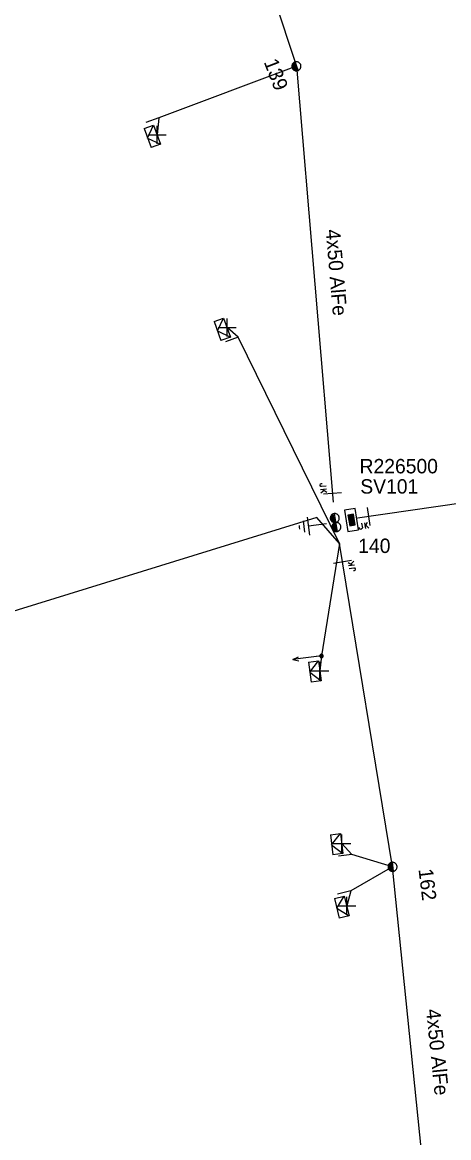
# Model space of a CAD drawing. Extents: x -544780 to -541582, y -1198995 to -1196551.
# Drawn here: x -542549.7 to -542520.2, y -1198913.7 to -1198836.4 of the extents above; entities that cross this region are included whole.
import ezdxf

# ---------------------------------------------------------------- set-up
doc = ezdxf.new("R2010")
doc.units = 0
for name, color, linetype in [('Vrstva 1', 7, 'Continuous'), ('Vrstva 13', 7, 'Continuous'), ('Vrstva 14', 7, 'Continuous'), ('Vrstva 15', 7, 'Continuous'), ('Vrstva 18', 7, 'Continuous'), ('Vrstva 2', 7, 'Continuous'), ('Vrstva 28', 7, 'Continuous'), ('Vrstva 29', 7, 'Continuous'), ('Vrstva 30', 7, 'Continuous'), ('Vrstva 31', 7, 'Continuous'), ('Vrstva 34', 7, 'Continuous'), ('Vrstva 54', 7, 'Continuous'), ('Vrstva 59', 7, 'Continuous'), ('Vrstva 8', 7, 'Continuous'), ('Vrstva 9', 7, 'Continuous')]:
    doc.layers.add(name, color=color, linetype=linetype)

# ---------------------------------------------------------------- blocks, each defined once
blk = doc.blocks.new('NN440')
at = {"layer": 'Vrstva 2'}
for points in [[(0.63, 0), (0.63, 0.06), (0.62, 0.13), (0.6, 0.19), (0.58, 0.25), (0.55, 0.31), (0.51, 0.37), (0.47, 0.42), (0.42, 0.46), (0.37, 0.51), (0.32, 0.54), (0.26, 0.57), (0.2, 0.59), (0.13, 0.61), (0.07, 0.62), (0, 0.63), (-0.06, 0.62), (-0.13, 0.61), (-0.19, 0.59), (-0.26, 0.57), (-0.31, 0.54), (-0.37, 0.51), (-0.42, 0.46), (-0.47, 0.42), (-0.51, 0.37), (-0.54, 0.31), (-0.57, 0.25), (-0.6, 0.19), (-0.62, 0.13), (-0.63, 0.06), (-0.63, 0), (-0.63, -0.07), (-0.62, -0.14), (-0.6, -0.2), (-0.57, -0.26), (-0.54, -0.32), (-0.51, -0.37), (-0.47, -0.43), (-0.42, -0.47), (-0.37, -0.51), (-0.31, -0.55), (-0.26, -0.58), (-0.19, -0.6), (-0.13, -0.62), (-0.06, -0.63), (0, -0.63), (0.07, -0.63), (0.13, -0.62), (0.2, -0.6), (0.26, -0.58), (0.32, -0.55), (0.37, -0.51), (0.42, -0.47), (0.47, -0.43), (0.51, -0.37), (0.55, -0.32), (0.58, -0.26), (0.6, -0.2), (0.62, -0.14), (0.63, -0.07), (0.63, 0)], [(-0.63, 0), (0.63, 0)], [(-0.6, -0.18), (0.57, -0.18)], [(-0.51, -0.32), (0.5, -0.32)], [(-0.37, -0.47), (0.35, -0.47)]]:
    blk.add_lwpolyline(points, dxfattribs=at)
blk = doc.blocks.new('NN450')
at = {"layer": 'Vrstva 2'}
for points in [[(0, 0), (0, 0.07), (-0.01, 0.13), (-0.03, 0.19), (-0.05, 0.25), (-0.08, 0.31), (-0.12, 0.37), (-0.16, 0.42), (-0.21, 0.46), (-0.26, 0.51), (-0.31, 0.54), (-0.37, 0.57), (-0.43, 0.59), (-0.5, 0.61), (-0.56, 0.62), (-0.63, 0.62), (-0.69, 0.62), (-0.75, 0.61), (-0.82, 0.59), (-0.88, 0.57), (-0.94, 0.54), (-0.99, 0.51), (-1.04, 0.46), (-1.09, 0.42), (-1.13, 0.37), (-1.17, 0.31), (-1.2, 0.25), (-1.22, 0.19), (-1.24, 0.13), (-1.25, 0.07), (-1.25, 0), (-1.25, -0.07), (-1.24, -0.13), (-1.22, -0.19), (-1.2, -0.25), (-1.17, -0.31), (-1.13, -0.37), (-1.09, -0.42), (-1.04, -0.46), (-0.99, -0.51), (-0.94, -0.54), (-0.88, -0.57), (-0.82, -0.59), (-0.75, -0.61), (-0.69, -0.62), (-0.62, -0.63), (-0.56, -0.62), (-0.5, -0.61), (-0.43, -0.59), (-0.37, -0.57), (-0.31, -0.54), (-0.26, -0.51), (-0.21, -0.46), (-0.16, -0.42), (-0.12, -0.37), (-0.08, -0.31), (-0.05, -0.25), (-0.03, -0.19), (-0.01, -0.13), (0, -0.07), (0, 0)], [(1.25, 0), (1.25, 0.07), (1.24, 0.13), (1.22, 0.19), (1.2, 0.25), (1.17, 0.31), (1.13, 0.37), (1.09, 0.42), (1.04, 0.46), (0.99, 0.51), (0.94, 0.54), (0.88, 0.57), (0.82, 0.59), (0.75, 0.61), (0.69, 0.62), (0.62, 0.62), (0.56, 0.62), (0.5, 0.61), (0.43, 0.59), (0.37, 0.57), (0.31, 0.54), (0.26, 0.51), (0.21, 0.46), (0.16, 0.42), (0.12, 0.37), (0.08, 0.31), (0.05, 0.25), (0.03, 0.19), (0.01, 0.13), (0, 0.07), (0, 0), (0, -0.07), (0.01, -0.13), (0.03, -0.19), (0.05, -0.25), (0.08, -0.31), (0.12, -0.37), (0.16, -0.42), (0.21, -0.46), (0.26, -0.51), (0.31, -0.54), (0.37, -0.57), (0.43, -0.59), (0.5, -0.61), (0.56, -0.62), (0.63, -0.63), (0.69, -0.62), (0.75, -0.61), (0.82, -0.59), (0.88, -0.57), (0.94, -0.54), (0.99, -0.51), (1.04, -0.46), (1.09, -0.42), (1.13, -0.37), (1.17, -0.31), (1.2, -0.25), (1.22, -0.19), (1.24, -0.13), (1.25, -0.07), (1.25, 0)], [(-1.25, 0), (1.25, 0)], [(-1.23, -0.16), (-0.02, -0.16)], [(-1.16, -0.32), (-0.09, -0.32)], [(-1.03, -0.47), (-0.22, -0.47)], [(0.02, -0.16), (1.23, -0.16)], [(0.09, -0.32), (1.16, -0.32)], [(0.22, -0.47), (1.03, -0.47)]]:
    blk.add_lwpolyline(points, dxfattribs=at)
blk = doc.blocks.new('NN560')
at = {"layer": 'Vrstva 2'}
for points in [[(1.999, -0.001), (1.59, 0.141)], [(0, -0.001), (1.999, -0.001)], [(1.999, -0.001), (1.59, -0.134)]]:
    blk.add_lwpolyline(points, dxfattribs=at)
blk = doc.blocks.new('NN840')
at = {"layer": 'Vrstva 15'}
for points in [[(0.003, 0.619), (0.003, -0.631)], [(-0.745, -0.71), (-0.745, -0.66)], [(-0.73, -0.764), (-0.745, -0.71)], [(-0.657, -0.798), (-0.73, -0.764)], [(-0.558, -0.764), (-0.627, -0.798)], [(-0.538, -0.71), (-0.558, -0.764)], [(-0.538, -0.385), (-0.538, -0.71)], [(-0.332, -0.385), (-0.332, -0.798)], [(-0.332, -0.641), (-0.125, -0.385)], [(-0.263, -0.557), (-0.091, -0.798)], [(-0.627, -0.798), (-0.657, -0.798)]]:
    blk.add_lwpolyline(points, dxfattribs=at)
blk = doc.blocks.new('NN800')
at = {"layer": 'Vrstva 1'}
for points in [[(-0.442, 0.442), (0.442, -0.442)], [(-0.442, -0.442), (0.442, 0.442)]]:
    blk.add_lwpolyline(points, dxfattribs=at)
blk = doc.blocks.new('NN620')
at = {"layer": 'Vrstva 8'}
for points in [[(0.752, 0.004), (-0.748, 0.004)], [(-0.748, 0.004), (-0.748, -0.746)], [(0.752, -0.746), (0.752, 0.004)], [(-0.748, -0.746), (0.752, -0.746)], [(0.368, -0.18), (-0.376, -0.18)], [(-0.376, -0.18), (-0.376, -0.558)], [(-0.376, -0.558), (0.368, -0.558)], [(0.321, -0.227), (-0.329, -0.227)], [(-0.329, -0.227), (-0.329, -0.51)], [(-0.329, -0.51), (0.321, -0.51)], [(0.274, -0.274), (-0.281, -0.274)], [(-0.281, -0.274), (-0.281, -0.463)], [(-0.281, -0.463), (0.274, -0.463)], [(0.227, -0.321), (-0.234, -0.321)], [(-0.234, -0.321), (-0.234, -0.416)], [(-0.234, -0.416), (0.227, -0.416)], [(-0.193, -0.369), (0.185, -0.369)], [(0.227, -0.416), (0.227, -0.321)], [(0.274, -0.463), (0.274, -0.274)], [(0.321, -0.51), (0.321, -0.227)], [(0.368, -0.558), (0.368, -0.18)]]:
    blk.add_lwpolyline(points, dxfattribs=at)
blk = doc.blocks.new('NN630')
at = {"layer": 'Vrstva 9'}
for points in [[(-0.003, -0.7), (-0.703, 0)], [(-0.703, -0.7), (-0.703, 0), (0.697, 0), (0.697, -0.7)], [(-0.703, -0.7), (0.697, -0.7)], [(-0.003, -0.7), (0.697, 0)]]:
    blk.add_lwpolyline(points, dxfattribs=at)
blk = doc.blocks.new('NN810')
at = {"layer": 'Vrstva 14'}
for points in [[(0.004, -0.64), (0.004, -1.89)], [(0.629, -1.89), (-0.621, -1.89)], [(0.388, -2.2), (-0.399, -2.2)], [(0.004, -2.515), (-0.124, -2.515)], [(0.137, -2.515), (0.004, -2.515)]]:
    blk.add_lwpolyline(points, dxfattribs=at)
blk = doc.blocks.new('NN500')
at = {"layer": 'Vrstva 2'}
for points in [[(0, -0.24), (0.02, -0.23), (0.05, -0.23), (0.07, -0.22), (0.09, -0.22), (0.12, -0.2), (0.14, -0.19), (0.16, -0.18), (0.17, -0.16), (0.19, -0.14), (0.2, -0.12), (0.21, -0.1), (0.22, -0.07), (0.23, -0.05), (0.23, -0.02), (0.23, 0), (0.23, 0.02), (0.23, 0.05), (0.22, 0.07), (0.21, 0.1), (0.2, 0.12), (0.19, 0.14), (0.17, 0.16), (0.16, 0.17), (0.14, 0.19), (0.12, 0.2), (0.09, 0.21), (0.07, 0.22), (0.05, 0.23), (0.02, 0.23), (0, 0.23), (-0.03, 0.23), (-0.05, 0.23), (-0.07, 0.22), (-0.1, 0.21), (-0.12, 0.2), (-0.14, 0.19), (-0.16, 0.17), (-0.18, 0.16), (-0.19, 0.14), (-0.2, 0.12), (-0.22, 0.1), (-0.22, 0.07), (-0.23, 0.05), (-0.23, 0.02), (-0.24, 0), (-0.23, -0.02), (-0.23, -0.05), (-0.22, -0.07), (-0.22, -0.1), (-0.2, -0.12), (-0.19, -0.14), (-0.18, -0.16), (-0.16, -0.18), (-0.14, -0.19), (-0.12, -0.2), (-0.1, -0.22), (-0.07, -0.22), (-0.05, -0.23), (-0.03, -0.23), (0, -0.24)], [(0, -0.24), (0.02, -0.23), (0.05, -0.23), (0.07, -0.22), (0.09, -0.22), (0.12, -0.2), (0.14, -0.19), (0.16, -0.18), (0.17, -0.16), (0.19, -0.14), (0.2, -0.12), (0.21, -0.1), (0.22, -0.07), (0.23, -0.05), (0.23, -0.02), (0.23, 0), (0.23, 0.02), (0.23, 0.05), (0.22, 0.07), (0.21, 0.1), (0.2, 0.12), (0.19, 0.14), (0.17, 0.16), (0.16, 0.17), (0.14, 0.19), (0.12, 0.2), (0.09, 0.21), (0.07, 0.22), (0.05, 0.23), (0.02, 0.23), (0, 0.23), (-0.03, 0.23), (-0.05, 0.23), (-0.07, 0.22), (-0.1, 0.21), (-0.12, 0.2), (-0.14, 0.19), (-0.16, 0.17), (-0.18, 0.16), (-0.19, 0.14), (-0.2, 0.12), (-0.22, 0.1), (-0.22, 0.07), (-0.23, 0.05), (-0.23, 0.02), (-0.24, 0), (-0.23, -0.02), (-0.23, -0.05), (-0.22, -0.07), (-0.22, -0.1), (-0.2, -0.12), (-0.19, -0.14), (-0.18, -0.16), (-0.16, -0.18), (-0.14, -0.19), (-0.12, -0.2), (-0.1, -0.22), (-0.07, -0.22), (-0.05, -0.23), (-0.03, -0.23), (0, -0.24)], [(0, -0.21), (0.02, -0.2), (0.04, -0.2), (0.06, -0.2), (0.08, -0.19), (0.1, -0.18), (0.12, -0.17), (0.14, -0.15), (0.15, -0.14), (0.16, -0.12), (0.18, -0.1), (0.19, -0.08), (0.19, -0.06), (0.2, -0.04), (0.2, -0.02), (0.2, 0), (0.2, 0.02), (0.2, 0.04), (0.19, 0.06), (0.19, 0.08), (0.18, 0.1), (0.16, 0.12), (0.15, 0.14), (0.14, 0.15), (0.12, 0.17), (0.1, 0.18), (0.08, 0.19), (0.06, 0.19), (0.04, 0.2), (0.02, 0.2), (0, 0.2), (-0.02, 0.2), (-0.04, 0.2), (-0.06, 0.19), (-0.08, 0.19), (-0.1, 0.18), (-0.12, 0.17), (-0.14, 0.15), (-0.15, 0.14), (-0.17, 0.12), (-0.18, 0.1), (-0.19, 0.08), (-0.2, 0.06), (-0.2, 0.04), (-0.21, 0.02), (-0.21, 0), (-0.21, -0.02), (-0.2, -0.04), (-0.2, -0.06), (-0.19, -0.08), (-0.18, -0.1), (-0.17, -0.12), (-0.15, -0.14), (-0.14, -0.15), (-0.12, -0.17), (-0.1, -0.18), (-0.08, -0.19), (-0.06, -0.2), (-0.04, -0.2), (-0.02, -0.2), (0, -0.21)], [(0, -0.18), (0.02, -0.18), (0.04, -0.17), (0.05, -0.17), (0.07, -0.16), (0.09, -0.15), (0.1, -0.14), (0.12, -0.13), (0.13, -0.12), (0.14, -0.1), (0.15, -0.09), (0.16, -0.07), (0.17, -0.05), (0.17, -0.04), (0.17, -0.02), (0.17, 0), (0.17, 0.02), (0.17, 0.04), (0.17, 0.05), (0.16, 0.07), (0.15, 0.09), (0.14, 0.1), (0.13, 0.12), (0.12, 0.13), (0.1, 0.14), (0.09, 0.15), (0.07, 0.16), (0.05, 0.17), (0.04, 0.17), (0.02, 0.17), (0, 0.18), (-0.02, 0.17), (-0.04, 0.17), (-0.06, 0.17), (-0.07, 0.16), (-0.09, 0.15), (-0.1, 0.14), (-0.12, 0.13), (-0.13, 0.12), (-0.14, 0.1), (-0.15, 0.09), (-0.16, 0.07), (-0.17, 0.05), (-0.17, 0.04), (-0.18, 0.02), (-0.18, 0), (-0.18, -0.02), (-0.17, -0.04), (-0.17, -0.05), (-0.16, -0.07), (-0.15, -0.09), (-0.14, -0.1), (-0.13, -0.12), (-0.12, -0.13), (-0.1, -0.14), (-0.09, -0.15), (-0.07, -0.16), (-0.06, -0.17), (-0.04, -0.17), (-0.02, -0.18), (0, -0.18)], [(0, -0.15), (0.01, -0.15), (0.03, -0.14), (0.04, -0.14), (0.06, -0.13), (0.07, -0.13), (0.08, -0.12), (0.1, -0.11), (0.11, -0.1), (0.12, -0.09), (0.13, -0.07), (0.13, -0.06), (0.14, -0.05), (0.14, -0.03), (0.14, -0.02), (0.14, 0), (0.14, 0.01), (0.14, 0.03), (0.14, 0.04), (0.13, 0.06), (0.13, 0.07), (0.12, 0.09), (0.11, 0.1), (0.1, 0.11), (0.08, 0.12), (0.07, 0.13), (0.06, 0.13), (0.04, 0.14), (0.03, 0.14), (0.01, 0.14), (0, 0.15), (-0.02, 0.14), (-0.03, 0.14), (-0.05, 0.14), (-0.06, 0.13), (-0.07, 0.13), (-0.09, 0.12), (-0.1, 0.11), (-0.11, 0.1), (-0.12, 0.09), (-0.13, 0.07), (-0.13, 0.06), (-0.14, 0.04), (-0.14, 0.03), (-0.15, 0.01), (-0.15, 0), (-0.15, -0.02), (-0.14, -0.03), (-0.14, -0.05), (-0.13, -0.06), (-0.13, -0.07), (-0.12, -0.09), (-0.11, -0.1), (-0.1, -0.11), (-0.09, -0.12), (-0.07, -0.13), (-0.06, -0.13), (-0.05, -0.14), (-0.03, -0.14), (-0.02, -0.15), (0, -0.15)], [(0, -0.12), (0.01, -0.12), (0.02, -0.11), (0.03, -0.11), (0.05, -0.11), (0.06, -0.1), (0.07, -0.09), (0.08, -0.09), (0.09, -0.08), (0.09, -0.07), (0.1, -0.06), (0.11, -0.05), (0.11, -0.04), (0.11, -0.02), (0.11, -0.01), (0.12, 0), (0.11, 0.01), (0.11, 0.02), (0.11, 0.04), (0.11, 0.05), (0.1, 0.06), (0.09, 0.07), (0.09, 0.08), (0.08, 0.09), (0.07, 0.09), (0.06, 0.1), (0.05, 0.11), (0.03, 0.11), (0.02, 0.11), (0.01, 0.12), (0, 0.12), (-0.01, 0.12), (-0.03, 0.11), (-0.04, 0.11), (-0.05, 0.11), (-0.06, 0.1), (-0.07, 0.09), (-0.08, 0.09), (-0.09, 0.08), (-0.1, 0.07), (-0.1, 0.06), (-0.11, 0.05), (-0.11, 0.04), (-0.12, 0.02), (-0.12, 0.01), (-0.12, 0), (-0.12, -0.01), (-0.12, -0.02), (-0.11, -0.04), (-0.11, -0.05), (-0.1, -0.06), (-0.1, -0.07), (-0.09, -0.08), (-0.08, -0.09), (-0.07, -0.09), (-0.06, -0.1), (-0.05, -0.11), (-0.04, -0.11), (-0.03, -0.11), (-0.01, -0.12), (0, -0.12)], [(0, -0.09), (0.01, -0.09), (0.02, -0.09), (0.03, -0.08), (0.03, -0.08), (0.04, -0.08), (0.05, -0.07), (0.06, -0.07), (0.06, -0.06), (0.07, -0.05), (0.07, -0.04), (0.08, -0.04), (0.08, -0.03), (0.08, -0.02), (0.09, -0.01), (0.09, 0), (0.09, 0.01), (0.08, 0.02), (0.08, 0.03), (0.08, 0.03), (0.07, 0.04), (0.07, 0.05), (0.06, 0.06), (0.06, 0.06), (0.05, 0.07), (0.04, 0.07), (0.03, 0.08), (0.03, 0.08), (0.02, 0.08), (0.01, 0.09), (0, 0.09), (-0.01, 0.09), (-0.02, 0.08), (-0.03, 0.08), (-0.04, 0.08), (-0.04, 0.07), (-0.05, 0.07), (-0.06, 0.06), (-0.07, 0.06), (-0.07, 0.05), (-0.08, 0.04), (-0.08, 0.03), (-0.08, 0.03), (-0.09, 0.02), (-0.09, 0.01), (-0.09, 0), (-0.09, -0.01), (-0.09, -0.02), (-0.08, -0.03), (-0.08, -0.04), (-0.08, -0.04), (-0.07, -0.05), (-0.07, -0.06), (-0.06, -0.07), (-0.05, -0.07), (-0.04, -0.08), (-0.04, -0.08), (-0.03, -0.08), (-0.02, -0.09), (-0.01, -0.09), (0, -0.09)], [(0, -0.06), (0, -0.06), (0.01, -0.06), (0.02, -0.05), (0.02, -0.05), (0.03, -0.05), (0.03, -0.05), (0.04, -0.04), (0.04, -0.04), (0.05, -0.03), (0.05, -0.03), (0.05, -0.02), (0.05, -0.02), (0.05, -0.01), (0.06, -0.01), (0.06, 0), (0.06, 0.01), (0.05, 0.01), (0.05, 0.02), (0.05, 0.02), (0.05, 0.03), (0.05, 0.03), (0.04, 0.04), (0.04, 0.04), (0.03, 0.05), (0.03, 0.05), (0.02, 0.05), (0.02, 0.05), (0.01, 0.06), (0, 0.06), (0, 0.06), (-0.01, 0.06), (-0.01, 0.06), (-0.02, 0.05), (-0.02, 0.05), (-0.03, 0.05), (-0.03, 0.05), (-0.04, 0.04), (-0.04, 0.04), (-0.05, 0.03), (-0.05, 0.03), (-0.05, 0.02), (-0.06, 0.02), (-0.06, 0.01), (-0.06, 0.01), (-0.06, 0), (-0.06, -0.01), (-0.06, -0.01), (-0.06, -0.02), (-0.05, -0.02), (-0.05, -0.03), (-0.05, -0.03), (-0.04, -0.04), (-0.04, -0.04), (-0.03, -0.05), (-0.03, -0.05), (-0.02, -0.05), (-0.02, -0.05), (-0.01, -0.06), (-0.01, -0.06), (0, -0.06)], [(0, -0.03), (0, -0.03), (0, -0.03), (0.01, -0.03), (0.01, -0.03), (0.01, -0.02), (0.02, -0.02), (0.02, -0.02), (0.02, -0.02), (0.02, -0.02), (0.02, -0.01), (0.02, -0.01), (0.03, -0.01), (0.03, -0.01), (0.03, 0), (0.03, 0), (0.03, 0), (0.03, 0.01), (0.03, 0.01), (0.02, 0.01), (0.02, 0.01), (0.02, 0.02), (0.02, 0.02), (0.02, 0.02), (0.02, 0.02), (0.01, 0.02), (0.01, 0.02), (0.01, 0.03), (0, 0.03), (0, 0.03), (0, 0.03), (0, 0.03), (-0.01, 0.03), (-0.01, 0.03), (-0.01, 0.02), (-0.02, 0.02), (-0.02, 0.02), (-0.02, 0.02), (-0.02, 0.02), (-0.02, 0.02), (-0.03, 0.01), (-0.03, 0.01), (-0.03, 0.01), (-0.03, 0.01), (-0.03, 0), (-0.03, 0), (-0.03, 0), (-0.03, -0.01), (-0.03, -0.01), (-0.03, -0.01), (-0.03, -0.01), (-0.02, -0.02), (-0.02, -0.02), (-0.02, -0.02), (-0.02, -0.02), (-0.02, -0.02), (-0.01, -0.03), (-0.01, -0.03), (-0.01, -0.03), (0, -0.03), (0, -0.03)], [(0.23, 0), (0.7, 0)]]:
    blk.add_lwpolyline(points, dxfattribs=at)
blk = doc.blocks.new('NN510')
at = {"layer": 'Vrstva 2'}
blk.add_lwpolyline([(0.001, 0.002), (0.001, 0.939)], dxfattribs=at)

msp = doc.modelspace()

# ---------------------------------------------------------------- linework, layer by layer
at = {"layer": 'Vrstva 1'}
for points in [[(-542597.24, -1198698.853), (-542596.829, -1198699.698), (-542586.651, -1198720.622), (-542572.542, -1198749.601), (-542561.272, -1198772.896), (-542547.621, -1198800.03), (-542541.854, -1198811.391), (-542535.435, -1198825.23), (-542530.734, -1198839.476), (-542528.184, -1198869.678)], [(-542504.472, -1198867.595), (-542526.501, -1198870.797)], [(-542521.346, -1198921.686), (-542524.075, -1198894.957), (-542527.76, -1198872.552)]]:
    msp.add_lwpolyline(points, dxfattribs=at)
at = {"layer": 'Vrstva 54'}
for points in [[(-542530.734, -1198839.476), (-542540.27, -1198843.041), (-542540.384, -1198844.218)], [(-542527.76, -1198872.552), (-542534.771, -1198858.242), (-542535.538, -1198857.584)], [(-542527.76, -1198872.552), (-542528.996, -1198880.345), (-542529.108, -1198881.385)], [(-542524.075, -1198894.957), (-542526.898, -1198894.099), (-542527.598, -1198893.346)], [(-542524.075, -1198894.957), (-542526.97, -1198896.633), (-542527.253, -1198897.668)]]:
    msp.add_lwpolyline(points, dxfattribs=at)
at = {"layer": 'Vrstva 59'}
msp.add_lwpolyline([(-542527.76, -1198872.552), (-542529.314, -1198870.741), (-542623.201, -1198899.779), (-542629.791, -1198887.614)], dxfattribs=at)

# ---------------------------------------------------------------- block references
at = {"layer": 'Vrstva 13'}
for name, p, xscale, yscale, rotation in [('NN440', (-542530.733, -1198839.475), 0.5, 0.49999999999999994, -69.00086106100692), ('NN450', (-542528.022, -1198871.097), 0.5000000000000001, 0.5, -79.99703331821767), ('NN500', (-542528.996, -1198880.345), 0.5, 0.49999999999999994, -172.73299991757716), ('NN440', (-542524.075, -1198894.957), 0.5000000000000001, 0.5, -83.07053056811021)]:
    msp.add_blockref(name, p, dxfattribs=dict(at, xscale=xscale, yscale=yscale, rotation=rotation))
for name, p, rotation in [('NN510', (-542540.269, -1198843.042), 110.04650552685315), ('NN510', (-542534.771, -1198858.243), 109.90061946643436), ('NN560', (-542528.996, -1198880.345), -172.7333750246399), ('NN510', (-542526.898, -1198894.1), 96.94117507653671), ('NN510', (-542526.969, -1198896.633), 103.48586944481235)]:
    msp.add_blockref(name, p, dxfattribs=dict(at, rotation=rotation))
at = {"layer": 'Vrstva 15', "rotation": -82.63618056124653}
msp.add_blockref('NN810', (-542528.021, -1198871.097), dxfattribs=at)
at = {"layer": 'Vrstva 18'}
for p, rotation in [((-542528.235, -1198869.084), -85.1746388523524), ((-542525.75, -1198870.676), 9.118380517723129), ((-542527.552, -1198873.82), 99.34054994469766)]:
    msp.add_blockref('NN840', p, dxfattribs=dict(at, rotation=rotation))
at = {"layer": 'Vrstva 28', "rotation": 99.18099996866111}
msp.add_blockref('NN620', (-542527.282, -1198870.977), dxfattribs=at)
at = {"layer": 'Vrstva 31'}
for p, rotation in [((-542540.384, -1198844.218), -69.95349447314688), ((-542535.538, -1198857.584), -70.09938053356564), ((-542529.108, -1198881.385), -82.73337501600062), ((-542527.598, -1198893.346), -83.05882499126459), ((-542527.253, -1198897.668), -76.51413052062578)]:
    msp.add_blockref('NN630', p, dxfattribs=dict(at, rotation=rotation))
at = {"layer": 'Vrstva 34'}
for p, rotation in [((-542540.384, -1198844.218), 45), ((-542535.538, -1198857.584), 44.99999995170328), ((-542529.108, -1198881.385), 45), ((-542527.598, -1198893.346), 45), ((-542527.253, -1198897.668), 45)]:
    msp.add_blockref('NN800', p, dxfattribs=dict(at, rotation=rotation))

# ---------------------------------------------------------------- texts
at = {"layer": 'Vrstva 14'}
for s, rotation, p in [('139', 290.999, (-542533.007, -1198839.173)), ('162', 276.929, (-542522.282, -1198895.136))]:
    msp.add_text(s, height=1, rotation=rotation, dxfattribs=at).set_placement(p)
msp.add_text('140', height=1, dxfattribs=at).set_placement((-542526.453, -1198873.208))
at = {"layer": 'Vrstva 2'}
for rotation, p in [(274.826, (-542528.706, -1198850.805)), (275.83, (-542521.761, -1198904.851))]:
    msp.add_text('4x50 AlFe', height=1, rotation=rotation, dxfattribs=at).set_placement(p)
at = {"layer": 'Vrstva 29'}
msp.add_text('R226500', height=1, rotation=0.02, dxfattribs=at).set_placement((-542526.361, -1198867.69))
at = {"layer": 'Vrstva 30'}
msp.add_text('SV101', height=1, rotation=0.02, dxfattribs=at).set_placement((-542526.31, -1198869.093))

doc.saveas('drawing.dxf')
